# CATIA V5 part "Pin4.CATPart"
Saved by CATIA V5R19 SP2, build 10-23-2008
Part number: Pin4
Revision: ANY
Definition: UNKNOWN
Nomenclature: Pin4
Source: Unknown
Bounding box of the stored display mesh (mm): x 0 to 18, y -3.5 to 3.5, z -3.5 to 3.5
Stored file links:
  Z:\fausse table rondelle-20220905T211342Z-001\fausse table rondelle\Pin4.CATPart
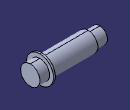
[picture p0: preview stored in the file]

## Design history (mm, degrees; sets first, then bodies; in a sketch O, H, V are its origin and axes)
AxisSystem1: origin (0, 0, 0), X (1, 0, 0), Y (0, 1, 0), Z (0, 0, 1)
Body1 "Rotation1" (main body)
  Solid1: solid without history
